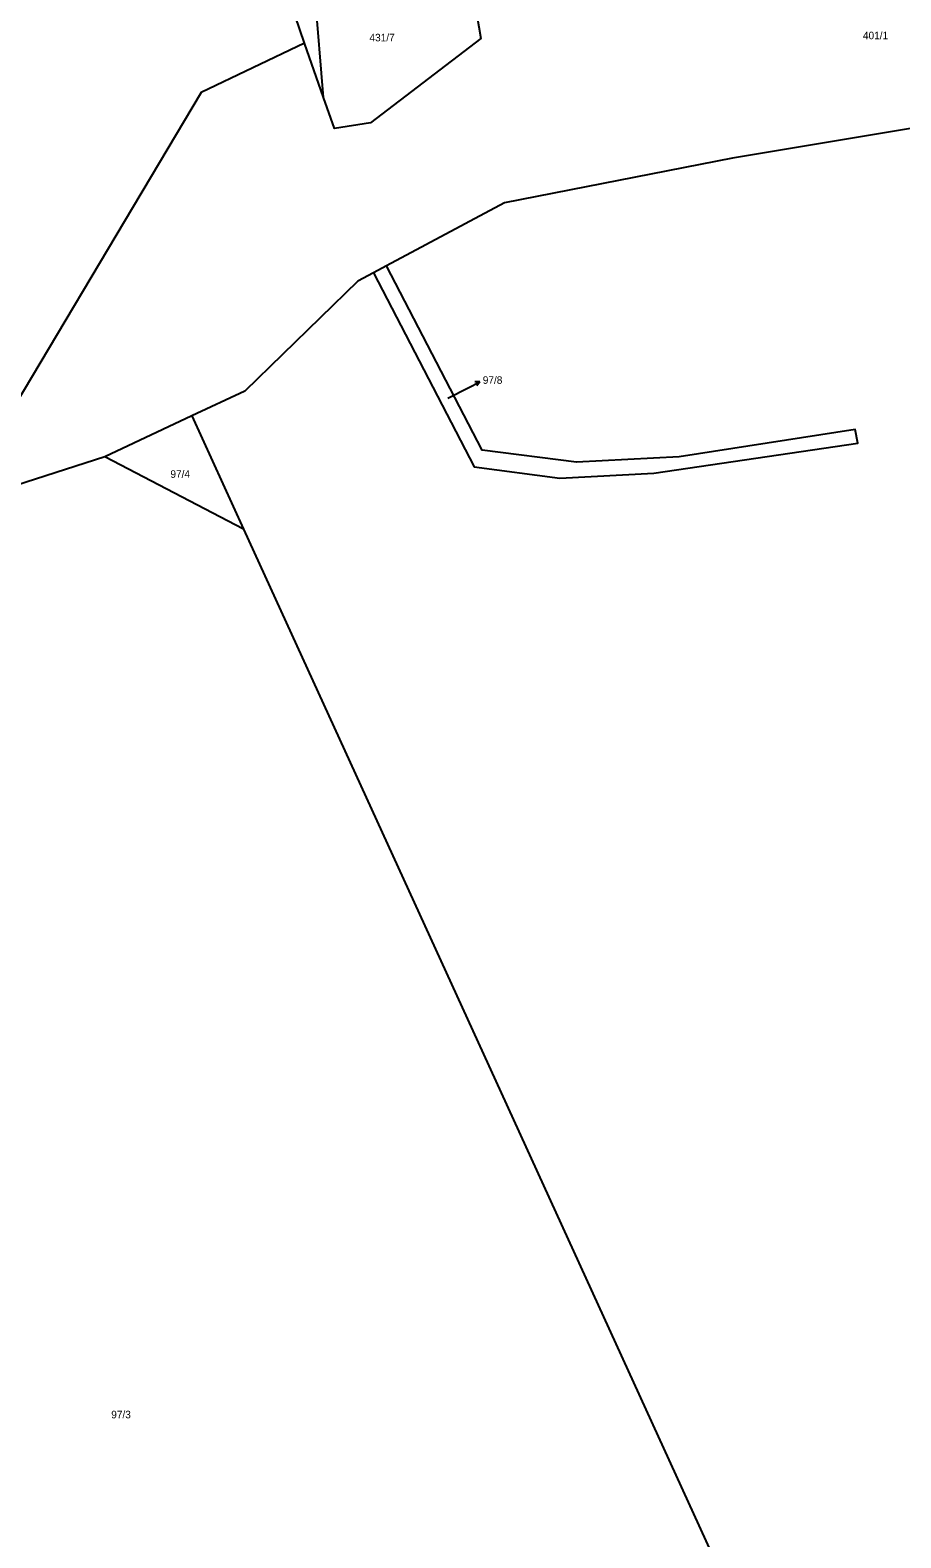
# Model space of a CAD drawing. Extents: x -880531 to -877616, y -1023932 to -1021350.
# Drawn here: x -879481.6 to -879285.2, y -1022931.1 to -1022591 of the extents above; entities that cross this region are included whole.
import ezdxf

# ---------------------------------------------------------------- set-up
doc = ezdxf.new("R2010")
doc.units = 0
for name, color, linetype in [('Hranice parcel', 7, 'Continuous'), ('Parcelní čísla', 7, 'Continuous'), ('Pop  PČ popisy', 7, 'Continuous')]:
    doc.layers.add(name, color=color, linetype=linetype)

msp = doc.modelspace()

# ---------------------------------------------------------------- linework, layer by layer
at = {"layer": 'Hranice parcel'}
for p, q in [((-879415.4, -1022606.17), (-879417.36, -1022582.52)), ((-879419.69, -1022593.89), (-879421.85, -1022587.72)), ((-879415.4, -1022606.17), (-879419.69, -1022593.89)), ((-879401.23, -1022644.14), (-879404.12, -1022645.69)), ((-879445.12, -1022677.99), (-879464.76, -1022687.24)), ((-879445.12, -1022677.99), (-879433.45, -1022703.53)), ((-879464.76, -1022687.24), (-879498.53, -1022698.08)), ((-879433.45, -1022703.53), (-879464.76, -1022687.24))]:
    msp.add_line(p, q, dxfattribs=at)
for points in [[(-879385.9, -1022583.53), (-879381.31, -1022584.98), (-879379.94, -1022592.88), (-879404.84, -1022611.84), (-879412.96, -1022613.16), (-879415.4, -1022606.17)], [(-879419.69, -1022593.89), (-879443.01, -1022605.06), (-879498.53, -1022698.08)], [(-878934.82, -1022632.19), (-879016.09, -1022607.53), (-879050.15, -1022605.63), (-879088.97, -1022611.57), (-879141.92, -1022616.89), (-879193.77, -1022622.98), (-879220.93, -1022632.47), (-879233.1, -1022621.8), (-879243.76, -1022616.91), (-879278.47, -1022612.38), (-879323.11, -1022619.86), (-879374.6, -1022629.94), (-879401.23, -1022644.14)], [(-879404.12, -1022645.69), (-879407.64, -1022647.56), (-879433.17, -1022672.37), (-879445.12, -1022677.99)], [(-879404.12, -1022645.69), (-879381.46, -1022689.47), (-879362.1, -1022692), (-879340.88, -1022690.92), (-879294.84, -1022684.15), (-879295.48, -1022681.03), (-879335.2, -1022687.21), (-879358.32, -1022688.43), (-879379.63, -1022685.69), (-879401.23, -1022644.14)], [(-879433.45, -1022703.53), (-879379.36, -1022821.92), (-879312.88, -1022967.45), (-879246.38, -1023112.98)]]:
    msp.add_lwpolyline(points, dxfattribs=at)
at = {"layer": 'Pop  PČ popisy'}
for p, q in [((-879387.35, -1022673.97), (-879382.81, -1022671.62)), ((-879382.81, -1022671.62), (-879380.136, -1022670.258)), ((-879380.136, -1022670.258), (-879381.256, -1022670.266)), ((-879380.136, -1022670.258), (-879380.801, -1022671.158))]:
    msp.add_line(p, q, dxfattribs=at)

# ---------------------------------------------------------------- texts
at = {"layer": 'Parcelní čísla'}
for s, p in [('401/1', (-879293.72, -1022593.01)), ('431/7', (-879405.053, -1022593.48)), ('97/8', (-879379.49, -1022670.74)), ('97/4', (-879449.96, -1022691.94)), ('97/3', (-879463.31, -1022904.09))]:
    msp.add_text(s, height=1.7, dxfattribs=at).set_placement(p)

doc.saveas('drawing.dxf')
